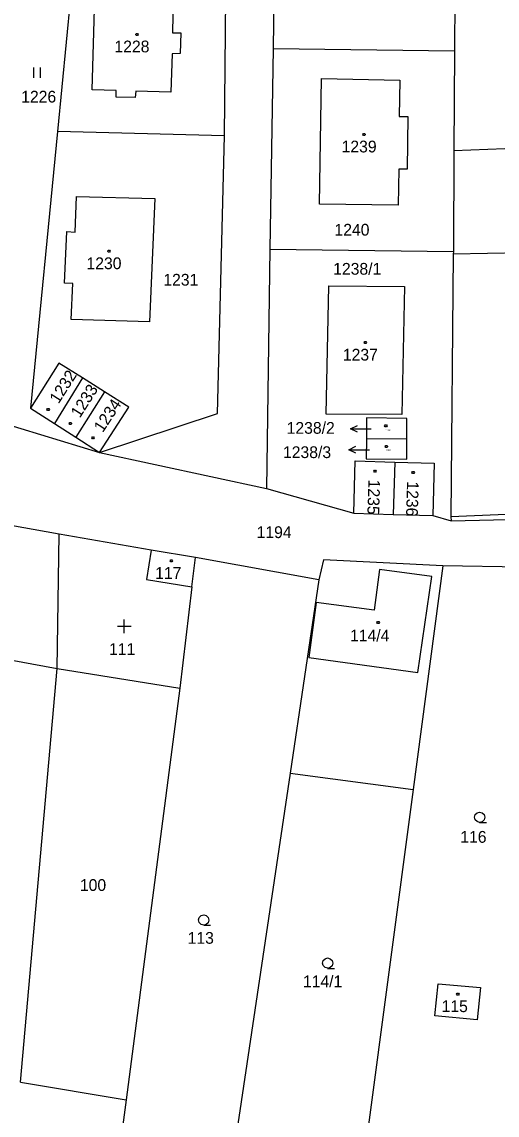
# Model space of a CAD drawing. Extents: x -609861 to -605046, y -1120287 to -1116307.
# Drawn here: x -607250.8 to -607182.1, y -1119072.1 to -1118914.2 of the extents above; entities that cross this region are included whole.
import ezdxf

# ---------------------------------------------------------------- set-up
doc = ezdxf.new("R2010")
doc.units = 0
for name, color, linetype in [('Vrstva 1', 7, 'Continuous'), ('Vrstva 2', 7, 'Continuous'), ('Vrstva 3', 7, 'Continuous'), ('Vrstva 4', 7, 'Continuous'), ('Vrstva 5', 7, 'Continuous'), ('Vrstva 7', 7, 'Continuous')]:
    doc.layers.add(name, color=color, linetype=linetype)

msp = doc.modelspace()

# ---------------------------------------------------------------- linework, layer by layer
at = {"layer": 'Vrstva 1'}
for p, q in [((-607213.83, -1118877.15), (-607214.48, -1118917.98)), ((-607188.08, -1118886.22), (-607188.27, -1118918.34)), ((-607221.5, -1118930.61), (-607221.22, -1118902.93)), ((-607243.11, -1118904.48), (-607245.62, -1118930)), ((-607240.62, -1118923.96), (-607240.19, -1118909.76)), ((-607228.88, -1118910.1), (-607229, -1118915.76)), ((-607229, -1118915.76), (-607227.81, -1118915.75)), ((-607227.81, -1118915.75), (-607227.91, -1118918.73)), ((-607214.48, -1118917.98), (-607214.94, -1118946.98)), ((-607214.48, -1118917.98), (-607188.27, -1118918.34)), ((-607229.06, -1118918.79), (-607229.24, -1118924.33)), ((-607227.91, -1118918.73), (-607229.06, -1118918.79)), ((-607188.27, -1118918.34), (-607188.35, -1118932.73)), ((-607207.75, -1118940.49), (-607207.49, -1118922.35)), ((-607207.49, -1118922.35), (-607196.17, -1118922.57)), ((-607196.17, -1118922.57), (-607196.24, -1118927.81)), ((-607237.12, -1118924.08), (-607240.62, -1118923.96)), ((-607237.15, -1118925.02), (-607237.12, -1118924.08)), ((-607234.28, -1118924.18), (-607234.37, -1118925.1)), ((-607229.24, -1118924.33), (-607234.28, -1118924.18)), ((-607234.37, -1118925.1), (-607237.15, -1118925.02)), ((-607196.24, -1118927.81), (-607195, -1118927.82)), ((-607195, -1118927.82), (-607195.1, -1118935.44)), ((-607245.62, -1118930), (-607249.49, -1118969.97)), ((-607221.5, -1118930.61), (-607245.62, -1118930)), ((-607222.48, -1118970.76), (-607221.5, -1118930.61)), ((-607188.35, -1118932.73), (-607156.76, -1118931.53)), ((-607188.35, -1118932.73), (-607188.43, -1118947.34)), ((-607196.33, -1118935.43), (-607196.4, -1118940.65)), ((-607195.1, -1118935.44), (-607196.33, -1118935.43)), ((-607243.08, -1118944.52), (-607242.86, -1118939.37)), ((-607242.86, -1118939.37), (-607231.56, -1118939.66)), ((-607231.56, -1118939.66), (-607232.3, -1118957.48)), ((-607196.4, -1118940.65), (-607207.75, -1118940.49)), ((-607244.59, -1118951.92), (-607244.27, -1118944.47)), ((-607244.27, -1118944.47), (-607243.08, -1118944.52)), ((-607214.94, -1118946.98), (-607215.44, -1118981.58)), ((-607214.94, -1118946.98), (-607188.43, -1118947.34)), ((-607188.46, -1118947.7), (-607188.78, -1118985.68)), ((-607155.04, -1118947.1), (-607188.46, -1118947.7)), ((-607188.43, -1118947.34), (-607188.46, -1118947.7)), ((-607243.4, -1118951.97), (-607244.59, -1118951.92)), ((-607243.62, -1118957.15), (-607243.4, -1118951.97)), ((-607206.83, -1118970.86), (-607206.4, -1118952.28)), ((-607206.4, -1118952.28), (-607195.5, -1118952.39)), ((-607195.5, -1118952.39), (-607195.89, -1118970.91)), ((-607232.3, -1118957.48), (-607243.62, -1118957.15)), ((-607245.4, -1118963.45), (-607249.49, -1118969.97)), ((-607241.99, -1118965.61), (-607245.4, -1118963.45)), ((-607241.99, -1118965.61), (-607246.05, -1118972.18)), ((-607238.83, -1118967.6), (-607241.99, -1118965.61)), ((-607238.83, -1118967.6), (-607242.95, -1118974.17)), ((-607235.33, -1118969.81), (-607238.83, -1118967.6)), ((-607249.49, -1118969.97), (-607246.05, -1118972.18)), ((-607239.53, -1118976.37), (-607235.33, -1118969.81)), ((-607239.53, -1118976.37), (-607222.48, -1118970.76)), ((-607195.89, -1118970.91), (-607206.83, -1118970.86)), ((-607200.99, -1118971.39), (-607201, -1118974.35)), ((-607195.14, -1118971.45), (-607200.99, -1118971.39)), ((-607195.16, -1118974.4), (-607195.14, -1118971.45)), ((-607253.77, -1118972.06), (-607239.53, -1118976.37)), ((-607246.05, -1118972.18), (-607242.95, -1118974.17)), ((-607242.95, -1118974.17), (-607239.53, -1118976.37)), ((-607201, -1118974.35), (-607201.03, -1118977.32)), ((-607201, -1118974.35), (-607195.16, -1118974.4)), ((-607195.18, -1118977.35), (-607195.16, -1118974.4)), ((-607239.53, -1118976.37), (-607215.44, -1118981.58)), ((-607202.8, -1118985.15), (-607202.61, -1118977.6)), ((-607202.61, -1118977.6), (-607196.91, -1118977.76)), ((-607201.03, -1118977.32), (-607195.18, -1118977.35)), ((-607196.91, -1118977.76), (-607197.11, -1118985.32)), ((-607196.91, -1118977.76), (-607191.22, -1118977.91)), ((-607191.22, -1118977.91), (-607191.42, -1118985.49)), ((-607215.44, -1118981.58), (-607202.8, -1118985.15)), ((-607151.26, -1118984.15), (-607188.78, -1118985.68)), ((-607245.35, -1118988.18), (-607261.05, -1118985.41)), ((-607202.8, -1118985.15), (-607197.11, -1118985.32)), ((-607197.11, -1118985.32), (-607191.42, -1118985.49)), ((-607191.42, -1118985.49), (-607188.74, -1118986.24)), ((-607188.78, -1118985.68), (-607188.74, -1118986.24)), ((-607188.74, -1118986.24), (-607151.08, -1118985.42)), ((-607245.68, -1119007.59), (-607245.35, -1118988.18)), ((-607232.06, -1118990.52), (-607245.35, -1118988.18)), ((-607232.06, -1118990.52), (-607232.74, -1118994.76)), ((-607225.67, -1118991.54), (-607232.06, -1118990.52)), ((-607226.19, -1118995.79), (-607225.67, -1118991.54)), ((-607207.86, -1118994.79), (-607225.67, -1118991.54)), ((-607207.17, -1118991.88), (-607207.86, -1118994.79)), ((-607189.96, -1118992.74), (-607207.17, -1118991.88)), ((-607199.09, -1118993.3), (-607199.87, -1118999.18)), ((-607191.56, -1118994.29), (-607199.09, -1118993.3)), ((-607189.96, -1118992.74), (-607194.26, -1119025.07)), ((-607171.77, -1118993.07), (-607189.96, -1118992.74)), ((-607232.74, -1118994.76), (-607226.19, -1118995.79)), ((-607207.86, -1118994.79), (-607212.02, -1119022.7)), ((-607193.57, -1119008.17), (-607191.56, -1118994.29)), ((-607226.19, -1118995.79), (-607227.96, -1119010.43)), ((-607208.23, -1118998.06), (-607209.29, -1119006.03)), ((-607199.87, -1118999.18), (-607208.23, -1118998.06)), ((-607264.64, -1119004.08), (-607245.68, -1119007.59)), ((-607209.29, -1119006.03), (-607193.57, -1119008.17)), ((-607250.96, -1119067.36), (-607245.68, -1119007.59)), ((-607245.68, -1119007.59), (-607227.96, -1119010.43)), ((-607227.96, -1119010.43), (-607235.7, -1119069.92)), ((-607212.02, -1119022.7), (-607223.16, -1119097.38)), ((-607194.26, -1119025.07), (-607202.87, -1119089.77)), ((-607191.09, -1119057.78), (-607190.65, -1119053.15)), ((-607190.65, -1119053.15), (-607184.5, -1119053.72)), ((-607184.5, -1119053.72), (-607184.98, -1119058.38)), ((-607184.98, -1119058.38), (-607191.09, -1119057.78)), ((-607250.96, -1119067.36), (-607235.7, -1119069.92)), ((-607235.7, -1119069.92), (-607238.79, -1119093.67))]:
    msp.add_line(p, q, dxfattribs=at)
at = {"layer": 'Vrstva 3'}
for p, q in [((-607249.06, -1118920.75), (-607249.06, -1118922.25)), ((-607248.06, -1118922.25), (-607248.06, -1118920.75)), ((-607236.96, -1119001.5), (-607234.96, -1119001.5)), ((-607235.96, -1119002.5), (-607235.96, -1119000.5))]:
    msp.add_line(p, q, dxfattribs=at)
for points in [[(-607184.64, -1119029.83), (-607185.02, -1119029.73), (-607185.29, -1119029.46), (-607185.39, -1119029.09), (-607185.29, -1119028.72), (-607185.02, -1119028.45), (-607184.65, -1119028.35), (-607184.28, -1119028.45), (-607184.01, -1119028.72), (-607183.91, -1119029.1), (-607184.01, -1119029.48), (-607184.28, -1119029.75), (-607184.66, -1119029.85), (-607183.66, -1119029.85)], [(-607224.48, -1119044.68), (-607224.86, -1119044.58), (-607225.13, -1119044.31), (-607225.23, -1119043.94), (-607225.13, -1119043.57), (-607224.86, -1119043.3), (-607224.49, -1119043.2), (-607224.12, -1119043.3), (-607223.85, -1119043.57), (-607223.75, -1119043.95), (-607223.85, -1119044.33), (-607224.12, -1119044.6), (-607224.5, -1119044.7), (-607223.5, -1119044.7)], [(-607206.59, -1119050.91), (-607206.97, -1119050.81), (-607207.24, -1119050.54), (-607207.34, -1119050.17), (-607207.24, -1119049.8), (-607206.97, -1119049.53), (-607206.6, -1119049.43), (-607206.23, -1119049.53), (-607205.96, -1119049.8), (-607205.86, -1119050.18), (-607205.96, -1119050.56), (-607206.23, -1119050.83), (-607206.61, -1119050.93), (-607205.61, -1119050.93)]]:
    msp.add_lwpolyline(points, dxfattribs=at)
at = {"layer": 'Vrstva 4'}
msp.add_line((-607212.02, -1119022.7), (-607194.26, -1119025.07), dxfattribs=at)
at = {"layer": 'Vrstva 5'}
for points in [[(-607234.05, -1118915.81), (-607233.96, -1118915.96), (-607234.05, -1118916.11), (-607234.23, -1118916.11), (-607234.32, -1118915.96), (-607234.23, -1118915.81)], [(-607201.24, -1118930.27), (-607201.15, -1118930.42), (-607201.24, -1118930.57), (-607201.42, -1118930.57), (-607201.51, -1118930.42), (-607201.42, -1118930.27)], [(-607238.09, -1118947.14), (-607238, -1118947.29), (-607238.09, -1118947.44), (-607238.27, -1118947.44), (-607238.36, -1118947.29), (-607238.27, -1118947.14)], [(-607201.06, -1118960.35), (-607200.97, -1118960.5), (-607201.06, -1118960.65), (-607201.24, -1118960.65), (-607201.33, -1118960.5), (-607201.24, -1118960.35)], [(-607246.87, -1118970.03), (-607246.78, -1118970.18), (-607246.87, -1118970.33), (-607247.05, -1118970.33), (-607247.14, -1118970.18), (-607247.05, -1118970.03)], [(-607243.66, -1118972.05), (-607243.57, -1118972.2), (-607243.66, -1118972.35), (-607243.84, -1118972.35), (-607243.93, -1118972.2), (-607243.84, -1118972.05)], [(-607198.1, -1118972.39), (-607198.01, -1118972.54), (-607198.1, -1118972.69), (-607198.28, -1118972.69), (-607198.37, -1118972.54), (-607198.28, -1118972.39)], [(-607240.4, -1118974.13), (-607240.31, -1118974.28), (-607240.4, -1118974.43), (-607240.58, -1118974.43), (-607240.67, -1118974.28), (-607240.58, -1118974.13)], [(-607198.02, -1118975.37), (-607197.93, -1118975.52), (-607198.02, -1118975.67), (-607198.2, -1118975.67), (-607198.29, -1118975.52), (-607198.2, -1118975.37)], [(-607199.67, -1118978.92), (-607199.58, -1118979.07), (-607199.67, -1118979.22), (-607199.85, -1118979.22), (-607199.94, -1118979.07), (-607199.85, -1118978.92)], [(-607194.16, -1118979.11), (-607194.07, -1118979.26), (-607194.16, -1118979.41), (-607194.34, -1118979.41), (-607194.43, -1118979.26), (-607194.34, -1118979.11)], [(-607229.08, -1118991.9), (-607228.99, -1118992.05), (-607229.08, -1118992.2), (-607229.26, -1118992.2), (-607229.35, -1118992.05), (-607229.26, -1118991.9)], [(-607199.2, -1119000.8), (-607199.11, -1119000.95), (-607199.2, -1119001.1), (-607199.38, -1119001.1), (-607199.47, -1119000.95), (-607199.38, -1119000.8)], [(-607187.71, -1119054.5), (-607187.62, -1119054.65), (-607187.71, -1119054.8), (-607187.89, -1119054.8), (-607187.98, -1119054.65), (-607187.89, -1119054.5)]]:
    msp.add_lwpolyline(points, close=True, dxfattribs=at)
at = {"layer": 'Vrstva 7'}
for p, q in [((-607203.29, -1118972.961), (-607200.29, -1118972.96)), ((-607203.53, -1118975.991), (-607200.53, -1118975.99))]:
    msp.add_line(p, q, dxfattribs=at)
for points in [[(-607202.29, -1118973.46), (-607203.29, -1118972.961), (-607202.29, -1118972.46)], [(-607202.53, -1118976.49), (-607203.53, -1118975.991), (-607202.53, -1118975.49)]]:
    msp.add_lwpolyline(points, dxfattribs=at)

# ---------------------------------------------------------------- texts
at = {"layer": 'Vrstva 2'}
for s, height, p in [('1228', 1.7, (-607237.387, -1118918.56)), ('1226', 1.7, (-607250.857, -1118925.81)), ('1239', 1.7, (-607204.577, -1118933.02)), ('1240', 1.7, (-607205.607, -1118945.04)), ('1230', 1.7, (-607241.427, -1118949.89)), ('1238/1', 1.7, (-607205.797, -1118950.69)), ('1231', 1.7, (-607230.327, -1118952.27)), ('1237', 1.7, (-607204.397, -1118963.1)), ('1238/2', 0.2, (-607198.294, -1118973.23)), ('1238/3', 0.2, (-607198.294, -1118976.14)), ('1194', 1.7, (-607216.857, -1118988.75)), ('117', 1.7, (-607231.507, -1118994.65)), ('114/4', 1.7, (-607203.357, -1119003.68)), ('111', 1.7, (-607238.167, -1119005.64)), ('116', 1.7, (-607187.437, -1119032.78)), ('100', 1.7, (-607242.377, -1119039.74)), ('113', 1.7, (-607226.817, -1119047.38)), ('114/1', 1.7, (-607210.167, -1119053.66)), ('115', 1.7, (-607190.137, -1119057.25))]:
    msp.add_text(s, height=height, dxfattribs=at).set_placement(p)
for s, rotation, p in [('1232', 57.58226, (-607245.459, -1118969.448)), ('1233', 57.58226, (-607242.389, -1118971.498)), ('1234', 56.72282, (-607239.075, -1118973.602)), ('1235', 268.20154, (-607200.702, -1118980.283)), ('1236', 268.20154, (-607195.122, -1118980.533))]:
    msp.add_text(s, height=1.7, rotation=rotation, dxfattribs=at).set_placement(p)
at = {"layer": 'Vrstva 7'}
for s, p in [('1238/2', (-607212.517, -1118973.68)), ('1238/3', (-607213.046, -1118977.19))]:
    msp.add_text(s, height=1.7, dxfattribs=at).set_placement(p)

doc.saveas('drawing.dxf')
